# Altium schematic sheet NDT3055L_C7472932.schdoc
size 127 x 101 mm
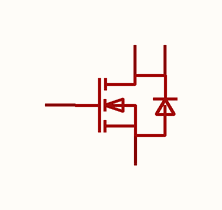
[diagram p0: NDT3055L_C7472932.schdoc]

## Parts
Q?  ndt3055l_c7472932  [SOT-223-3_L6.4-W3.5-P2.30-LS7.0-BR]  (value not drawn)

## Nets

Not connected (* = marked no-connect by the designer): Q? 1(G) 2(D) 3(S) 4(D)

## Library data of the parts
Q? = ndt3055l_c7472932: 漏源电压(Vdss):60V;连续漏极电流(Id):-;导通电阻(RDS(on)):100mΩ@4.5V,1.5A;耗散功率(Pd):3W;阈值电压(Vgs(th)):3V;; Manufacturer: TECH PUBLIC(台舟); AddInBom: yes; ModelId: 6654433eca7b4e7f8ee05e27058a22e4; ModelTransform: 251.968,275.59,0,90,0,0,-3.937,0,0; Drain to Source Voltage: 60V; Pd - Power Dissipation: 3W; Gate Threshold Voltage (Vgs(th)@Id): 3V; Gate Charge(Qg): 17nC; Input Capacitance(Ciss@Vds): 530pF@25V; Reverse Transfer Capacitance (Crss@Vds): 50pF@25V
